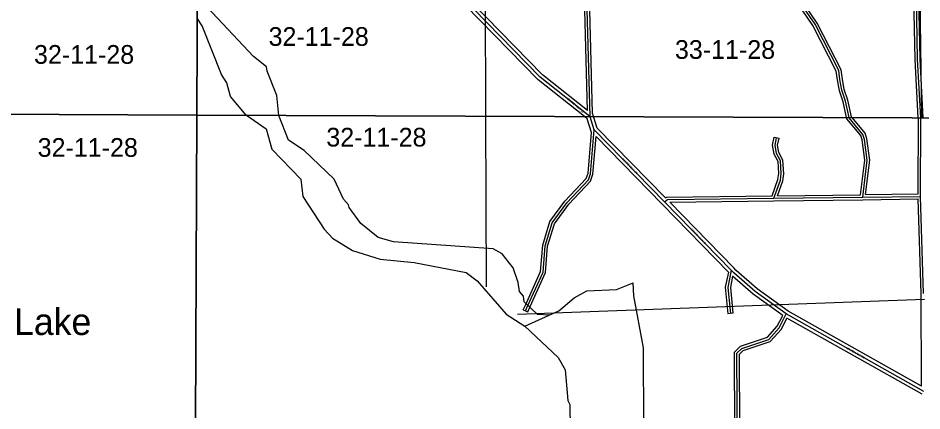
# Model space of a CAD drawing. Extents: x 457167 to 656239, y 1787309 to 1969297.
# Drawn here: x 495028 to 505894, y 1874980 to 1879700 of the extents above; entities that cross this region are included whole.
import ezdxf

# ---------------------------------------------------------------- set-up
doc = ezdxf.new("R2010")
doc.units = 0
for name, color, linetype in [('Level 1', 7, 'Continuous'), ('Level 2', 7, 'Continuous'), ('Level 22', 7, 'Continuous'), ('Level 23', 7, 'Continuous'), ('Level 31', 7, 'Continuous'), ('Level 32', 7, 'Continuous'), ('Level 34', 7, 'Continuous'), ('Level 41', 7, 'Continuous'), ('Level 5', 7, 'Continuous'), ('Level 63', 7, 'Continuous'), ('Level 7', 7, 'Continuous')]:
    doc.layers.add(name, color=color, linetype=linetype)

msp = doc.modelspace()

# ---------------------------------------------------------------- linework, layer by layer
at = {"layer": 'Level 1'}
for p, q in [((505893.545, 1878502.071), (505856.495, 1881080.316)), ((500638.213, 1880989.311), (500647.529, 1878521.731)), ((500647.53, 1878521.731), (500655.249, 1876472.488)), ((501031.869, 1876142.069), (505924.819, 1876324.78))]:
    msp.add_line(p, q, dxfattribs=at)
at = {"layer": 'Level 22'}
for p, q in [((501903.946, 1878514.786), (501901.111, 1878517.033)), ((501953.554, 1878356.757), (501903.946, 1878514.786)), ((502800.682, 1877493.956), (501953.554, 1878356.757)), ((503601.88, 1876670.272), (502800.682, 1877493.956)), ((505918.162, 1875214.614), (504262.76, 1876146.461))]:
    msp.add_line(p, q, dxfattribs=at)
for points in [[(501901.11, 1878517.033), (501305.918, 1878988.928), (499379.378, 1880963.629)], [(504262.76, 1876146.461), (503888.756, 1876414.543), (503631.026, 1876640.334), (503601.88, 1876670.272)]]:
    msp.add_lwpolyline(points, dxfattribs=at)
at = {"layer": 'Level 23'}
for p, q in [((501945.215, 1878516.868), (501932.85, 1878556.261)), ((501869.463, 1878491.077), (501836.418, 1878517.276)), ((501920.969, 1878327.005), (501869.463, 1878491.078)), ((501988.837, 1878377.916), (501945.216, 1878516.868)), ((502811.733, 1877539.796), (501988.837, 1878377.916)), ((502772.14, 1877465.931), (501976.914, 1878275.869)), ((503566.931, 1876648.834), (502772.01, 1877466.065)), ((503630.553, 1876698.162), (502861.069, 1877489.243)), ((505888.134, 1875277.42), (504284.288, 1876180.245)), ((505898.223, 1875179.937), (504270.894, 1876095.979))]:
    msp.add_line(p, q, dxfattribs=at)
for points in [[(501836.417, 1878517.276), (501279.068, 1878959.169), (499353.502, 1880932.87)], [(501871.895, 1878591.244), (501332.767, 1879018.687), (499468.607, 1880929.45)], [(504219.846, 1876128.005), (503863.865, 1876383.169), (503617.975, 1876598.588)], [(504284.287, 1876180.245), (503913.646, 1876445.917), (503658.58, 1876669.375), (503630.541, 1876698.176)]]:
    msp.add_lwpolyline(points, dxfattribs=at)
at = {"layer": 'Level 31'}
for p, q in [((505841.743, 1879205.555), (505783.693, 1882390.977)), ((501903.885, 1878517.024), (501838.43, 1880971.136)), ((505880.357, 1878502.12), (505841.743, 1879205.555)), ((501903.946, 1878514.786), (501903.886, 1878517.024)), ((504113.826, 1877534.735), (505182.841, 1877548.189)), ((505182.841, 1877548.189), (505877.064, 1877557.371)), ((505914.333, 1876390.289), (505877.064, 1877557.371))]:
    msp.add_line(p, q, dxfattribs=at)
for points in [[(505019.255, 1878505.348), (504974.394, 1878703.973), (504931.017, 1878833.245), (504908, 1878962.069), (504893.49, 1879070.859), (504608.801, 1879625.856), (504355.19, 1879999.267), (504300.055, 1880052.585), (503989.975, 1880074.22), (503864.267, 1880139.465), (503765.141, 1880248.239), (503739.171, 1880353.803), (503736.969, 1880514.909), (503666.991, 1880594.471), (503333.06, 1880694.031)], [(505182.841, 1877548.189), (505235.551, 1877992.711), (505203.804, 1878243.391), (505184.001, 1878302.382), (505020.02, 1878501.963), (505019.256, 1878505.348)], [(505877.064, 1877557.371), (505880.559, 1878498.467), (505880.358, 1878502.12)], [(501128.451, 1876183.056), (501157.674, 1876248.026), (501338.468, 1876649.099), (501364.606, 1876965.724), (501449.107, 1877240.651), (501625.091, 1877481.741), (501884.564, 1877755.941), (501909.691, 1877830.747), (501953.554, 1878356.757)], [(504113.826, 1877534.735), (504192.664, 1877752.598), (504202.533, 1877831.833), (504192.98, 1877984.966), (504144.352, 1878074.257), (504128.219, 1878174.326), (504147.031, 1878262.251)], [(502800.682, 1877493.956), (502833.872, 1877518.91), (504113.826, 1877534.735)], [(503601.88, 1876670.272), (503560.311, 1876464.985), (503591.15, 1876149.942)], [(504244.826, 1872309.368), (504215.745, 1872511.672), (504125.748, 1872912.412), (503993.891, 1873346.415), (503711.801, 1873689.033), (503679.011, 1873839.352), (503669.047, 1875673.249), (503727.51, 1875731.556), (504053.106, 1875838.585), (504178.721, 1875979.892), (504262.76, 1876146.461)]]:
    msp.add_lwpolyline(points, dxfattribs=at)
at = {"layer": 'Level 32'}
for p, q in [((505871.73, 1879206.65), (505813.69, 1882391.524)), ((505811.757, 1879204.457), (505754.68, 1882336.559)), ((501871.895, 1878591.244), (501809.24, 1880940.359)), ((501932.85, 1878556.261), (501869.23, 1880941.618)), ((505850.306, 1878502.233), (505811.758, 1879204.458)), ((505910.41, 1878502.008), (505871.729, 1879206.649)), ((504117.696, 1878268.528), (504176.368, 1878255.974)), ((504156.785, 1877565.277), (505156.149, 1877577.855)), ((505216.663, 1877578.638), (505847.174, 1877586.978)), ((502861.069, 1877489.243), (504114.197, 1877504.737)), ((504114.204, 1877504.736), (505183.218, 1877518.191)), ((505183.237, 1877518.191), (505848.02, 1877526.984)), ((505884.335, 1876389.757), (505848.02, 1877526.983)), ((505888.131, 1875285.057), (505884.335, 1876389.757)), ((501101.09, 1876195.363), (501155.811, 1876170.75)), ((503621.008, 1876152.865), (503561.292, 1876147.019)), ((505888.135, 1875277.42), (505888.131, 1875285.146))]:
    msp.add_line(p, q, dxfattribs=at)
for points in [[(504988.473, 1878505.463), (504945.467, 1878695.876), (504901.873, 1878825.794), (504878.35, 1878957.445), (504864.437, 1879061.767), (504582.949, 1879610.524), (504332.111, 1879979.852), (504287.06, 1880023.418), (503981.68, 1880044.726), (503845.697, 1880115.302), (503737.831, 1880233.667), (503709.22, 1880349.966), (503707.123, 1880503.417), (503650.158, 1880568.185), (503324.489, 1880665.281)], [(505056.18, 1878505.209), (505047.715, 1878515.511), (505003.32, 1878712.07), (504960.162, 1878840.695), (504937.649, 1878966.692), (504922.545, 1879079.95), (504634.654, 1879641.187), (504378.27, 1880018.682), (504313.051, 1880081.751), (503998.272, 1880103.715), (503882.837, 1880163.627), (503792.452, 1880262.811), (503769.121, 1880357.641), (503766.815, 1880526.401), (503683.824, 1880620.758), (503415.43, 1880700.777)], [(505156.149, 1877577.855), (505205.327, 1877992.591), (505174.415, 1878236.667), (505157.317, 1878287.602), (504992.324, 1878488.414), (504988.474, 1878505.463)], [(505216.662, 1877578.638), (505265.776, 1877992.831), (505233.192, 1878250.115), (505210.686, 1878317.161), (505056.181, 1878505.209)], [(505847.174, 1877586.979), (505850.556, 1878497.701), (505850.307, 1878502.233)], [(501101.09, 1876195.363), (501130.318, 1876260.344), (501308.994, 1876656.717), (501334.974, 1876971.431), (501421.909, 1877254.275), (501601.987, 1877500.972), (501858.23, 1877771.76), (501880.096, 1877836.857), (501920.969, 1878327.004)], [(501155.811, 1876170.75), (501185.029, 1876235.71), (501367.942, 1876641.481), (501394.236, 1876960.017), (501476.305, 1877227.026), (501648.196, 1877462.509), (501910.898, 1877740.121), (501939.285, 1877824.636), (501976.914, 1878275.87)], [(504092.686, 1877564.476), (504163.309, 1877759.644), (504172.416, 1877832.761), (504163.451, 1877976.459), (504115.551, 1878064.416), (504097.706, 1878175.103), (504117.696, 1878268.528)], [(504156.785, 1877565.277), (504222.019, 1877745.552), (504232.65, 1877830.905), (504222.507, 1877993.473), (504173.153, 1878084.099), (504158.732, 1878173.549), (504176.368, 1878255.974)], [(502811.732, 1877539.796), (502823.687, 1877548.786), (504092.686, 1877564.476)], [(503566.931, 1876648.833), (503530.016, 1876466.535), (503561.292, 1876147.019)], [(503617.975, 1876598.588), (503590.607, 1876463.435), (503621.008, 1876152.865)], [(504210.313, 1872338.617), (504186.216, 1872506.242), (504096.72, 1872904.754), (503966.926, 1873331.967), (503684.034, 1873675.56), (503649.027, 1873836.038), (503638.979, 1875685.631), (503711.371, 1875757.83), (504036.056, 1875864.56), (504153.699, 1875996.9), (504219.846, 1876128.005)], [(504274.521, 1872313.636), (504245.273, 1872517.101), (504154.776, 1872920.07), (504020.856, 1873360.863), (503739.568, 1873702.507), (503708.993, 1873842.667), (503699.116, 1875660.866), (503743.649, 1875705.281), (504070.156, 1875812.61), (504203.743, 1875962.885), (504270.894, 1876095.978)]]:
    msp.add_lwpolyline(points, dxfattribs=at)
at = {"layer": 'Level 5'}
for p, q in [((497770.787, 1878530.595), (497769.159, 1878532.519)), ((497769.676, 1878535.846), (497774.495, 1878532.499)), ((501121.162, 1875999.26), (501413.356, 1876131.695))]:
    msp.add_line(p, q, dxfattribs=at)
for points in [[(497769.158, 1878532.519), (497579.769, 1878756.268), (497538.645, 1878923.121), (497472.281, 1879023.383), (497240.726, 1879607.684), (497182.664, 1879699.575)], [(497774.496, 1878532.499), (498010.903, 1878368.336), (498076.846, 1878126.383), (498425.826, 1877766.812), (498450.15, 1877558.309), (498707.328, 1877165.686), (498807.001, 1877057.016), (499048.296, 1876906.187), (499381.424, 1876805.07), (499789.771, 1876762.114), (500414.633, 1876643.41), (500547.686, 1876542.951), (500896.537, 1876141.699), (501121.162, 1875999.26)], [(501413.356, 1876131.695), (501530.227, 1876181.347), (501714.119, 1876339.151), (501864.431, 1876422.025), (502222.956, 1876437.59), (502423.289, 1876520.293)], [(501121.162, 1875999.26), (501520.093, 1875622.849), (501602.996, 1875472.537), (501635.161, 1875105.642), (501660.011, 1875055.522), (501680.378, 1873596.611)]]:
    msp.add_lwpolyline(points, dxfattribs=at)
at = {"layer": 'Level 63'}
for points in [[(457410.247, 1878726.517), (497176.541, 1878534.741), (497371.387, 1923990.389), (457653.971, 1924182.684), (457410.247, 1878726.517)], [(497176.54, 1878534.741), (536942.563, 1878385.707), (537088.612, 1923840.983), (497371.386, 1923990.389), (497176.54, 1878534.741)], [(457166.97, 1833271.563), (496982.081, 1833080.334), (497176.54, 1878534.741), (457410.246, 1878726.517), (457166.97, 1833271.563)], [(496982.082, 1833080.334), (536796.8, 1832931.691), (536942.564, 1878385.707), (497176.541, 1878534.741), (496982.082, 1833080.334)]]:
    msp.add_lwpolyline(points, dxfattribs=at)
at = {"layer": 'Level 7'}
for p, q in [((498162.853, 1878531.044), (498161.483, 1878534.6)), ((498162.594, 1878529.32), (498162.421, 1878531.046))]:
    msp.add_line(p, q, dxfattribs=at)
for points in [[(498162.42, 1878531.046), (498138.368, 1878771.176), (498022.61, 1879063.301), (498014.44, 1879113.351), (497856.434, 1879238.893), (497299.793, 1879832.57), (497183.479, 1879958.011)], [(501413.356, 1876131.695), (501271.673, 1876140.483), (501113.739, 1876291.064), (501105.628, 1876357.755), (501055.806, 1876416.275), (501039.466, 1876524.706), (500981.662, 1876699.968), (500848.808, 1876867.119), (500740.636, 1876925.798), (499540.464, 1877012.985), (499357.231, 1877063.593), (499149.345, 1877230.973), (499008.251, 1877423.164), (499000.01, 1877456.545), (498941.888, 1877523.395), (498825.964, 1877765.537), (498468.584, 1878108.467), (498277.239, 1878234.107), (498162.854, 1878531.044)], [(502971.681, 1870724.775), (502872.267, 1870916.836), (502859.026, 1871992.282), (502659.739, 1872242.993), (502643.756, 1872451.466), (502845.495, 1872975.996), (502862.623, 1873125.989), (502856.117, 1873701.227), (502798.742, 1874009.861), (502749.38, 1874210.093), (502633.425, 1874443.876), (502625.324, 1874518.936), (502592.073, 1874552.376), (502551.21, 1874802.59), (502545.85, 1875736.293), (502431.141, 1876361.871), (502423.289, 1876520.293)]]:
    msp.add_lwpolyline(points, dxfattribs=at)

# ---------------------------------------------------------------- texts
at = {"layer": 'Level 2'}
for s, p in [('32-11-28', (498039.305, 1879366.533)), ('33-11-28', (502924.505, 1879210.324)), ('32-11-28', (495219.362, 1879151.058)), ('32-11-28', (498733.6, 1878156.846)), ('32-11-28', (495263.357, 1878033.28))]:
    msp.add_text(s, height=225, dxfattribs=at).set_placement(p)
at = {"layer": 'Level 34'}
for rotation, p in [(318.2557167, (501630.21, 1878722.391)), (314.4740917, (502284.79, 1878001.553)), (314.2064222, (503109.31, 1877158.741)), (330.6235584, (504980.583, 1875728.046))]:
    msp.add_text('STATE HWY 20', height=25, rotation=rotation, dxfattribs=at).set_placement(p)
at = {"layer": 'Level 41'}
msp.add_text('Crescent Lake', height=320, dxfattribs=at).set_placement((493148.931, 1875892.211))

doc.saveas('drawing.dxf')
